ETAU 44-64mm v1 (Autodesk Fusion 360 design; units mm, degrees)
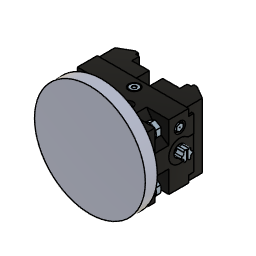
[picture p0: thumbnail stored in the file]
parameter "Ouverture" = 60
base_feature "Base Feature1"
base_feature "Base Feature1"
base_feature "Base Feature1"
position "Position1"
joint_origin "JointOrigin1" OffsetX 0 OffsetY 0 OffsetZ 0
joint_origin "JointOrigin2" OffsetX 0 OffsetY 0 OffsetZ 0
joint_origin "JointOrigin1" OffsetX 0 OffsetY 0 OffsetZ 0
joint "Assemble1" alignOffsetX 0 alignOffsetY 0 alignOffsetZ -7.3 (= "-Ouverture / 2 + 22.7 mm")
joint "Assemble2" alignOffsetX 0 alignOffsetY 0 alignOffsetZ 7.3 (= "Ouverture / 2 - 22.7 mm")
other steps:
create_component "CreateComponent1"
create_component "CreateComponent2"
create_component "CreateComponent3"
joint_origin "JointOrigin2" OffsetX 0 OffsetY 0 OffsetZ 0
